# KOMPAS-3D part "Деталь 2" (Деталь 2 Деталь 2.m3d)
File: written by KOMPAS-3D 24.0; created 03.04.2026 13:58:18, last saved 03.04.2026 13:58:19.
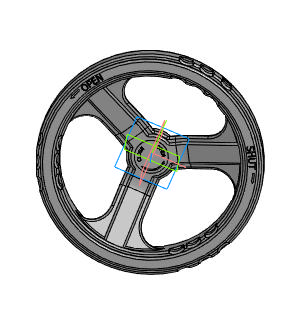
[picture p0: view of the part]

Document properties: Автор: R2D2; Полное имя файла: E:\Работа\Зайцев\Аксессуары для пневмоприводов\Ручной дублер DN.ru\MON2-450-T28-ISO Ручной дублер DN.ru\исходные материалы\Деталь 2 Деталь 2.m3d

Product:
- Part/product: Деталь 2
    Масса: 2.361285
    additional columns: Типовые

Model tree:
1. Операция без истории:1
